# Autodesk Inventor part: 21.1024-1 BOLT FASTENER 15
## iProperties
Created: 2006-12
Part Number: 21.1024-1 BOLT FASTENER 15
Document SubType Name: Modeling
Designer: Andy Moles
Material: Aluminum-6061
Mass: 5.32319 g
Surface Area: 13.8401 cm^2
Volume: 1.96428 cm^3
Density: 2.71 g/cm^3
Author: Andy Moles
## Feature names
1. Extrusion1
2. Extrusion2
3. Extrusion3
